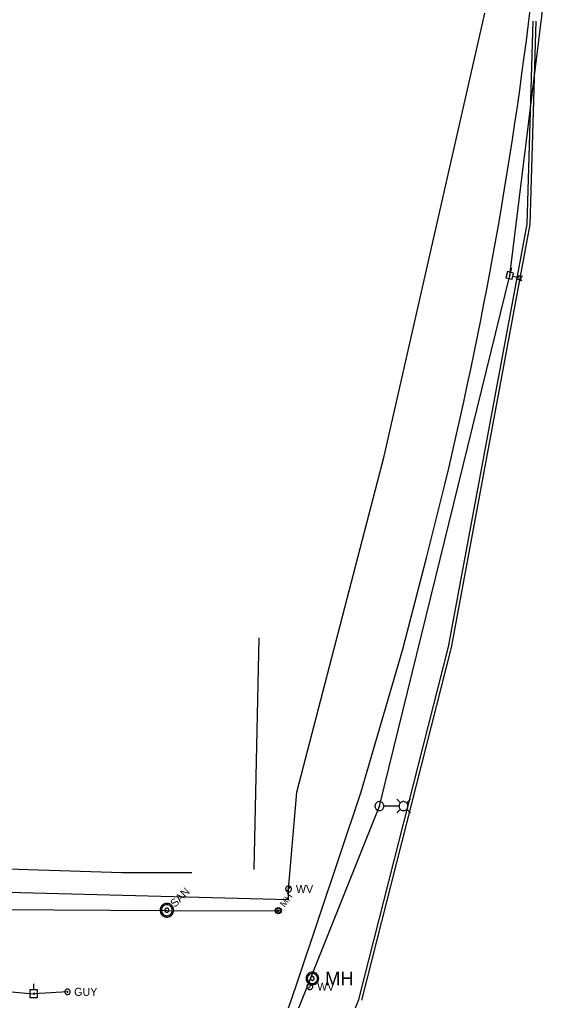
# Model space of a CAD drawing. Extents: x 596028 to 606371, y 330010 to 403088.
# Drawn here: x 604605.3 to 604862.3, y 331373.7 to 331845.6 of the extents above; entities that cross this region are included whole.
import ezdxf

# ---------------------------------------------------------------- set-up
doc = ezdxf.new("R2010")
doc.units = 0
for name, color, linetype in [('E_LTG', 7, 'Continuous'), ('E_LTG_CID', 7, 'Continuous'), ('E_UTL_EGuyWire', 7, 'Continuous'), ('E_UTL_EPowerPole', 7, 'Continuous'), ('E_UTL_G_UG', 7, 'Continuous'), ('E_UTL_Overhead', 7, 'Continuous'), ('E_UTL_SAN_MH', 7, 'Continuous'), ('E_UTL_SAN_UG', 7, 'Continuous'), ('E_UTL_W', 7, 'Continuous'), ('E_UTL_W_MH', 7, 'Continuous'), ('E_UTL_W_UG', 7, 'Continuous')]:
    doc.layers.add(name, color=color, linetype=linetype)

msp = doc.modelspace()

# ---------------------------------------------------------------- linework, layer by layer
at = {"layer": 'E_LTG'}
for points in [[(604845.03, 331721.53), (604842.73, 331722.07)], [(604845.16, 331720.88), (604844.32, 331720.36)], [(604845.43, 331722.05), (604844.91, 331722.89)], [(604846.71, 331721.13), (604846.73, 331721.29), (604846.72, 331721.45), (604846.68, 331721.61), (604846.61, 331721.76), (604846.52, 331721.89), (604846.4, 331722), (604846.26, 331722.09), (604846.11, 331722.15), (604845.95, 331722.18), (604845.79, 331722.18), (604845.63, 331722.14), (604845.48, 331722.08), (604845.34, 331721.99), (604845.23, 331721.88), (604845.13, 331721.75), (604845.07, 331721.6), (604845.03, 331721.44), (604845.02, 331721.28), (604845.05, 331721.12), (604845.1, 331720.97), (604845.18, 331720.83), (604845.29, 331720.7), (604845.42, 331720.61), (604845.56, 331720.53), (604845.72, 331720.49), (604845.88, 331720.47), (604846.04, 331720.49), (604846.2, 331720.53), (604846.34, 331720.61), (604846.47, 331720.71), (604846.57, 331720.83), (604846.65, 331720.97), (604846.71, 331721.13)], [(604846.32, 331720.61), (604846.84, 331719.77)], [(604846.6, 331721.77), (604847.43, 331722.29)], [(604780.7, 331467.17), (604780.66, 331467.58), (604780.54, 331467.97), (604780.35, 331468.34), (604780.09, 331468.67), (604779.78, 331468.94), (604779.42, 331469.15), (604779.03, 331469.28), (604778.62, 331469.34), (604778.21, 331469.32), (604777.81, 331469.22), (604777.43, 331469.05), (604777.1, 331468.81), (604776.81, 331468.51), (604776.59, 331468.16), (604776.43, 331467.78), (604776.35, 331467.37), (604776.35, 331466.96), (604776.43, 331466.55), (604776.59, 331466.17), (604776.81, 331465.82), (604777.1, 331465.52), (604777.43, 331465.28), (604777.81, 331465.11), (604778.21, 331465.01), (604778.62, 331464.99), (604779.03, 331465.05), (604779.42, 331465.19), (604779.78, 331465.39), (604780.09, 331465.66), (604780.35, 331465.99), (604780.54, 331466.36), (604780.66, 331466.75), (604780.7, 331467.17)], [(604788.6, 331468.69), (604786.82, 331470.47)], [(604792.3, 331467.17), (604792.26, 331467.58), (604792.14, 331467.97), (604791.95, 331468.34), (604791.7, 331468.67), (604791.39, 331468.94), (604791.03, 331469.15), (604790.64, 331469.28), (604790.23, 331469.34), (604789.81, 331469.32), (604789.41, 331469.22), (604789.04, 331469.05), (604788.7, 331468.81), (604788.41, 331468.51), (604788.19, 331468.16), (604788.04, 331467.78), (604787.96, 331467.37), (604787.96, 331466.96), (604788.04, 331466.55), (604788.19, 331466.17), (604788.41, 331465.82), (604788.7, 331465.52), (604789.04, 331465.28), (604789.41, 331465.11), (604789.81, 331465.01), (604790.23, 331464.99), (604790.64, 331465.05), (604791.03, 331465.19), (604791.39, 331465.39), (604791.7, 331465.66), (604791.95, 331465.99), (604792.14, 331466.36), (604792.26, 331466.75), (604792.3, 331467.17)], [(604791.65, 331468.69), (604793.43, 331470.47)], [(604778.69, 331467.17), (604778.68, 331467.2), (604778.67, 331467.23), (604778.66, 331467.26), (604778.64, 331467.28), (604778.62, 331467.3), (604778.59, 331467.32), (604778.56, 331467.33), (604778.53, 331467.33), (604778.5, 331467.33), (604778.47, 331467.32), (604778.44, 331467.31), (604778.41, 331467.29), (604778.39, 331467.27), (604778.37, 331467.24), (604778.36, 331467.21), (604778.35, 331467.18), (604778.35, 331467.15), (604778.36, 331467.12), (604778.37, 331467.09), (604778.39, 331467.06), (604778.41, 331467.04), (604778.44, 331467.02), (604778.47, 331467.01), (604778.5, 331467), (604778.53, 331467), (604778.56, 331467), (604778.59, 331467.01), (604778.62, 331467.03), (604778.64, 331467.05), (604778.66, 331467.08), (604778.67, 331467.1), (604778.68, 331467.13), (604778.69, 331467.17)], [(604787.91, 331467.17), (604780.73, 331467.17)], [(604788.6, 331465.64), (604786.82, 331463.87)], [(604791.65, 331465.64), (604793.43, 331463.87)]]:
    msp.add_lwpolyline(points, dxfattribs=at)
at = {"layer": 'E_LTG_CID'}
msp.add_lwpolyline([(604680.92, 331223.31), (604778.52, 331467.17), (604841.28, 331722.49), (604873.72, 331985.14), (604875.05, 331997.61), (604878.05, 332072.5), (604879.01, 332133.59), (604879.29, 332193.85), (604879.03, 332249.73), (604879.6, 332255.02), (604881.21, 332520.43)], dxfattribs=at)
at = {"layer": 'E_UTL_EGuyWire'}
msp.add_line((604628.38, 331377.81), (604612.18, 331376.89), dxfattribs=at)
for points in [[(604629.67, 331377.81), (604629.64, 331378.05), (604629.57, 331378.28), (604629.46, 331378.5), (604629.31, 331378.69), (604629.13, 331378.85), (604628.92, 331378.97), (604628.69, 331379.05), (604628.44, 331379.09), (604628.2, 331379.08), (604627.96, 331379.02), (604627.74, 331378.92), (604627.54, 331378.78), (604627.37, 331378.6), (604627.24, 331378.39), (604627.15, 331378.17), (604627.11, 331377.93), (604627.11, 331377.68), (604627.15, 331377.44), (604627.24, 331377.22), (604627.37, 331377.01), (604627.54, 331376.84), (604627.74, 331376.69), (604627.96, 331376.59), (604628.2, 331376.53), (604628.44, 331376.52), (604628.69, 331376.56), (604628.92, 331376.64), (604629.13, 331376.76), (604629.31, 331376.92), (604629.46, 331377.11), (604629.57, 331377.33), (604629.64, 331377.56), (604629.67, 331377.81)], [(604628.54, 331377.81), (604628.54, 331377.84), (604628.53, 331377.86), (604628.52, 331377.89), (604628.5, 331377.92), (604628.48, 331377.94), (604628.45, 331377.95), (604628.42, 331377.96), (604628.39, 331377.97), (604628.36, 331377.96), (604628.33, 331377.96), (604628.3, 331377.94), (604628.28, 331377.93), (604628.26, 331377.9), (604628.24, 331377.88), (604628.23, 331377.85), (604628.22, 331377.82), (604628.22, 331377.79), (604628.23, 331377.76), (604628.24, 331377.73), (604628.26, 331377.71), (604628.28, 331377.68), (604628.3, 331377.67), (604628.33, 331377.65), (604628.36, 331377.65), (604628.39, 331377.65), (604628.42, 331377.65), (604628.45, 331377.66), (604628.48, 331377.67), (604628.5, 331377.69), (604628.52, 331377.72), (604628.53, 331377.75), (604628.54, 331377.77), (604628.54, 331377.81)]]:
    msp.add_lwpolyline(points, dxfattribs=at)
at = {"layer": 'E_UTL_EPowerPole'}
for points in [[(604840.12, 331724.35), (604839.4, 331721.35)], [(604843.11, 331723.64), (604840.12, 331724.35)], [(604841.61, 331723.99), (604842.17, 331726.35)], [(604839.4, 331721.35), (604842.39, 331720.64)], [(604841.47, 331722.45), (604841.48, 331722.48), (604841.48, 331722.52), (604841.47, 331722.56), (604841.45, 331722.59), (604841.43, 331722.62), (604841.4, 331722.65), (604841.37, 331722.67), (604841.34, 331722.68), (604841.3, 331722.69), (604841.26, 331722.69), (604841.22, 331722.68), (604841.19, 331722.67), (604841.16, 331722.65), (604841.13, 331722.62), (604841.11, 331722.59), (604841.09, 331722.56), (604841.08, 331722.52), (604841.08, 331722.48), (604841.09, 331722.44), (604841.1, 331722.41), (604841.12, 331722.38), (604841.14, 331722.35), (604841.17, 331722.32), (604841.21, 331722.31), (604841.24, 331722.3), (604841.28, 331722.29), (604841.32, 331722.3), (604841.36, 331722.31), (604841.39, 331722.32), (604841.42, 331722.35), (604841.44, 331722.38), (604841.46, 331722.41), (604841.47, 331722.45)], [(604842.39, 331720.64), (604843.11, 331723.64)], [(604612.15, 331378.73), (604612.15, 331381.64)], [(604614, 331378.73), (604610.31, 331378.73)], [(604610.31, 331378.73), (604610.31, 331375.04)], [(604610.31, 331375.04), (604614, 331375.04)], [(604612.42, 331376.89), (604612.42, 331376.93), (604612.41, 331376.97), (604612.38, 331377.02), (604612.36, 331377.05), (604612.32, 331377.08), (604612.28, 331377.1), (604612.24, 331377.12), (604612.2, 331377.12), (604612.15, 331377.12), (604612.11, 331377.11), (604612.06, 331377.09), (604612.03, 331377.07), (604612, 331377.03), (604611.97, 331377), (604611.96, 331376.95), (604611.95, 331376.91), (604611.95, 331376.86), (604611.96, 331376.82), (604611.97, 331376.78), (604612, 331376.74), (604612.03, 331376.71), (604612.06, 331376.68), (604612.11, 331376.66), (604612.15, 331376.65), (604612.2, 331376.65), (604612.24, 331376.65), (604612.28, 331376.67), (604612.32, 331376.69), (604612.36, 331376.72), (604612.38, 331376.76), (604612.41, 331376.8), (604612.42, 331376.84), (604612.42, 331376.89)], [(604614, 331375.04), (604614, 331378.73)]]:
    msp.add_lwpolyline(points, dxfattribs=at)
at = {"layer": 'E_UTL_G_UG'}
msp.add_lwpolyline([(604462.99, 331439.17), (604493.85, 331439.57), (604559.63, 331439.45), (604599.63, 331437), (604654.59, 331435.18), (604688.27, 331435.25)], dxfattribs=at)
at = {"layer": 'E_UTL_Overhead'}
msp.add_lwpolyline([(604364.63, 331391.63), (604461.8, 331390.13), (604612.18, 331376.89)], dxfattribs=at)
at = {"layer": 'E_UTL_SAN_MH'}
for points in [[(604678.55, 331419.4), (604678.06, 331419.8), (604677.51, 331420.1), (604676.91, 331420.29), (604676.29, 331420.36), (604675.67, 331420.32), (604675.06, 331420.16), (604674.5, 331419.88), (604673.99, 331419.51), (604673.57, 331419.04), (604673.24, 331418.51), (604673.03, 331417.92), (604672.92, 331417.3), (604672.94, 331416.67), (604673.07, 331416.06), (604673.32, 331415.48), (604673.67, 331414.96), (604674.11, 331414.52), (604674.63, 331414.17), (604675.21, 331413.92), (604675.82, 331413.79), (604676.45, 331413.77), (604677.07, 331413.88), (604677.65, 331414.1), (604678.19, 331414.42), (604678.65, 331414.85), (604679.03, 331415.35), (604679.3, 331415.91), (604679.47, 331416.52), (604679.51, 331417.14), (604679.44, 331417.77), (604679.25, 331418.36), (604678.95, 331418.91), (604678.55, 331419.4)], [(604678.08, 331418.93), (604677.69, 331419.25), (604677.25, 331419.49), (604676.77, 331419.64), (604676.28, 331419.7), (604675.78, 331419.67), (604675.29, 331419.54), (604674.84, 331419.32), (604674.44, 331419.02), (604674.1, 331418.65), (604673.84, 331418.22), (604673.66, 331417.75), (604673.58, 331417.25), (604673.59, 331416.75), (604673.7, 331416.26), (604673.9, 331415.8), (604674.18, 331415.38), (604674.53, 331415.03), (604674.95, 331414.75), (604675.41, 331414.55), (604675.9, 331414.44), (604676.4, 331414.43), (604676.9, 331414.52), (604677.37, 331414.69), (604677.8, 331414.95), (604678.17, 331415.29), (604678.47, 331415.69), (604678.69, 331416.14), (604678.82, 331416.63), (604678.85, 331417.13), (604678.79, 331417.63), (604678.64, 331418.1), (604678.4, 331418.54), (604678.08, 331418.93)], [(604676.91, 331417.77), (604676.77, 331417.89), (604676.6, 331417.98), (604676.42, 331418.03), (604676.24, 331418.05), (604676.05, 331418.04), (604675.87, 331417.99), (604675.7, 331417.91), (604675.55, 331417.8), (604675.42, 331417.66), (604675.32, 331417.5), (604675.26, 331417.32), (604675.23, 331417.14), (604675.23, 331416.95), (604675.27, 331416.76), (604675.34, 331416.59), (604675.45, 331416.43), (604675.58, 331416.3), (604675.74, 331416.2), (604675.91, 331416.12), (604676.1, 331416.08), (604676.28, 331416.08), (604676.47, 331416.11), (604676.65, 331416.17), (604676.81, 331416.27), (604676.95, 331416.4), (604677.06, 331416.55), (604677.14, 331416.72), (604677.19, 331416.9), (604677.2, 331417.09), (604677.18, 331417.28), (604677.12, 331417.45), (604677.03, 331417.62), (604676.91, 331417.77)]]:
    msp.add_lwpolyline(points, dxfattribs=at)
for radius in [1.5, 1.2, 0.45]:
    msp.add_circle((604729.82, 331416.86), radius, dxfattribs=at)
at = {"layer": 'E_UTL_SAN_UG'}
msp.add_line((604476.65, 331417.91), (604676.22, 331417.01), dxfattribs=at)
msp.add_lwpolyline([(604676.22, 331417.01), (604729.83, 331416.85)], dxfattribs=at)
at = {"layer": 'E_UTL_W'}
for points in [[(604736.19, 331427.27), (604736.16, 331427.54), (604736.09, 331427.8), (604735.96, 331428.04), (604735.8, 331428.26), (604735.59, 331428.43), (604735.36, 331428.57), (604735.1, 331428.66), (604734.83, 331428.7), (604734.56, 331428.68), (604734.3, 331428.62), (604734.05, 331428.51), (604733.83, 331428.35), (604733.64, 331428.15), (604733.5, 331427.92), (604733.4, 331427.67), (604733.35, 331427.41), (604733.35, 331427.14), (604733.4, 331426.87), (604733.5, 331426.62), (604733.64, 331426.39), (604733.83, 331426.19), (604734.05, 331426.04), (604734.3, 331425.92), (604734.56, 331425.86), (604734.83, 331425.85), (604735.1, 331425.89), (604735.36, 331425.97), (604735.59, 331426.11), (604735.8, 331426.29), (604735.96, 331426.5), (604736.09, 331426.74), (604736.16, 331427), (604736.19, 331427.27)], [(604733.76, 331426.26), (604735.77, 331428.28)], [(604746.41, 331380.33), (604746.39, 331380.6), (604746.31, 331380.86), (604746.19, 331381.11), (604746.02, 331381.32), (604745.81, 331381.5), (604745.58, 331381.63), (604745.32, 331381.72), (604745.05, 331381.76), (604744.78, 331381.75), (604744.52, 331381.68), (604744.27, 331381.57), (604744.05, 331381.41), (604743.86, 331381.22), (604743.72, 331380.99), (604743.62, 331380.74), (604743.57, 331380.47), (604743.57, 331380.2), (604743.62, 331379.93), (604743.72, 331379.68), (604743.86, 331379.45), (604744.05, 331379.26), (604744.27, 331379.1), (604744.52, 331378.99), (604744.78, 331378.92), (604745.05, 331378.91), (604745.32, 331378.95), (604745.58, 331379.04), (604745.81, 331379.17), (604746.02, 331379.35), (604746.19, 331379.56), (604746.31, 331379.8), (604746.39, 331380.06), (604746.41, 331380.33)], [(604743.98, 331379.33), (604745.99, 331381.34)]]:
    msp.add_lwpolyline(points, dxfattribs=at)
at = {"layer": 'E_UTL_W_MH'}
for points in [[(604749.29, 331384.24), (604749.24, 331384.82), (604749.08, 331385.38), (604748.81, 331385.89), (604748.45, 331386.35), (604748.01, 331386.73), (604747.51, 331387.02), (604746.96, 331387.21), (604746.38, 331387.29), (604745.8, 331387.26), (604745.24, 331387.13), (604744.71, 331386.89), (604744.24, 331386.55), (604743.84, 331386.13), (604743.52, 331385.64), (604743.31, 331385.1), (604743.2, 331384.53), (604743.2, 331383.95), (604743.31, 331383.38), (604743.52, 331382.84), (604743.84, 331382.35), (604744.24, 331381.93), (604744.71, 331381.59), (604745.24, 331381.35), (604745.8, 331381.22), (604746.38, 331381.19), (604746.96, 331381.27), (604747.51, 331381.46), (604748.01, 331381.75), (604748.45, 331382.13), (604748.81, 331382.59), (604749.08, 331383.1), (604749.24, 331383.66), (604749.29, 331384.24)], [(604748.68, 331384.24), (604748.64, 331384.7), (604748.51, 331385.15), (604748.29, 331385.56), (604748.01, 331385.93), (604747.66, 331386.23), (604747.25, 331386.46), (604746.81, 331386.62), (604746.35, 331386.68), (604745.89, 331386.66), (604745.44, 331386.55), (604745.02, 331386.36), (604744.64, 331386.09), (604744.32, 331385.75), (604744.07, 331385.36), (604743.89, 331384.93), (604743.81, 331384.47), (604743.81, 331384.01), (604743.89, 331383.55), (604744.07, 331383.12), (604744.32, 331382.73), (604744.64, 331382.39), (604745.02, 331382.12), (604745.44, 331381.93), (604745.89, 331381.82), (604746.35, 331381.8), (604746.81, 331381.86), (604747.25, 331382.02), (604747.66, 331382.25), (604748.01, 331382.55), (604748.29, 331382.92), (604748.51, 331383.33), (604748.64, 331383.78), (604748.68, 331384.24)], [(604747.16, 331384.24), (604747.14, 331384.41), (604747.09, 331384.58), (604747.01, 331384.74), (604746.9, 331384.87), (604746.77, 331384.99), (604746.62, 331385.07), (604746.45, 331385.13), (604746.28, 331385.16), (604746.11, 331385.15), (604745.94, 331385.11), (604745.78, 331385.03), (604745.64, 331384.93), (604745.52, 331384.81), (604745.42, 331384.66), (604745.36, 331384.5), (604745.33, 331384.33), (604745.33, 331384.15), (604745.36, 331383.98), (604745.42, 331383.82), (604745.52, 331383.67), (604745.64, 331383.55), (604745.78, 331383.45), (604745.94, 331383.37), (604746.11, 331383.33), (604746.28, 331383.32), (604746.45, 331383.35), (604746.62, 331383.41), (604746.77, 331383.49), (604746.9, 331383.61), (604747.01, 331383.74), (604747.09, 331383.9), (604747.14, 331384.07), (604747.16, 331384.24)]]:
    msp.add_lwpolyline(points, dxfattribs=at)
at = {"layer": 'E_UTL_W_UG'}
for p, q in [((604718.14, 331436.66), (604720.58, 331548.2)), ((604768.62, 331374.17), (604811.69, 331543.82)), ((604770.07, 331373.8), (604813.14, 331543.45)), ((604649.65, 331083.04), (604768.62, 331374.17)), ((604768.62, 331374.17), (604768.62, 331374.17))]:
    msp.add_line(p, q, dxfattribs=at)
for points in [[(604738.76, 331473.89), (604780.74, 331635.62), (604829.31, 331848.68)], [(604811.69, 331543.82), (604849.6, 331747.14), (604852.44, 331844.91)], [(604813.16, 331543.55), (604851.09, 331746.98), (604853.94, 331844.87)], [(604739.44, 331383.52), (604769.61, 331473.63), (604789.83, 331542.72), (604801.22, 331586.62), (604808.3, 331614.89)], [(604734.76, 331427.27), (604738.76, 331473.89)], [(604459.92, 331427.24), (604507.36, 331428.16), (604734.76, 331422.27), (604734.76, 331422.27)], [(604734.76, 331422.27), (604734.76, 331427.27)]]:
    msp.add_lwpolyline(points, dxfattribs=at)
for centre, radius, start, end in [((602844.56, 332093.42), 2021.2, 346.30299, 353.58065), ((602817.06, 332055.12), 2036.32, 331.76571, 340.74254)]:
    msp.add_arc(centre, radius, start, end, dxfattribs=at)

# ---------------------------------------------------------------- texts
at = {"layer": 'E_UTL_EGuyWire'}
msp.add_text('GUY', height=3.85, dxfattribs=at).set_placement((604631.59, 331375.88))
at = {"layer": 'E_UTL_SAN_MH'}
for s, height, rotation, p in [('SAN', 3.849, 45, (604680.11, 331418.21)), ('MH', 3.24, 53.5849, (604732.9, 331418.31))]:
    msp.add_text(s, height=height, rotation=rotation, dxfattribs=at).set_placement(p)
at = {"layer": 'E_UTL_W'}
for p in [(604738.33, 331425.35), (604748.55, 331378.41)]:
    msp.add_text('WV', height=3.85, dxfattribs=at).set_placement(p)
at = {"layer": 'E_UTL_W_MH'}
msp.add_text('MH', height=6.6, dxfattribs=at).set_placement((604752.35, 331380.94))

doc.saveas('drawing.dxf')
